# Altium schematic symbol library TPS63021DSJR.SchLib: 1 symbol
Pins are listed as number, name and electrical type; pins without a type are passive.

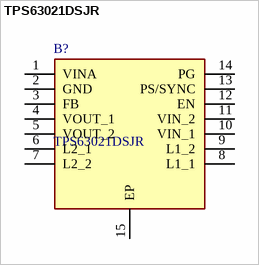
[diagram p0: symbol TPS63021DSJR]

## TPS63021DSJR
designator B?
High Efficiency Single Inductor Buck-Boost Converter with 4A Switch; Manufacturer_Name: Texas Instruments; Geometry.Height: 1mm
footprint SON50P300X400X100-15N-D
pins: 1 VINA, 2 GND, 3 FB, 4 VOUT_1, 5 VOUT_2, 6 L2_1, 7 L2_2, 8 L1_1, 9 L1_2, 10 VIN_1, 11 VIN_2, 12 EN, 13 PS/SYNC, 14 PG, 15 EP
